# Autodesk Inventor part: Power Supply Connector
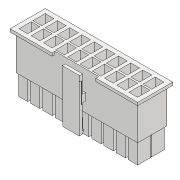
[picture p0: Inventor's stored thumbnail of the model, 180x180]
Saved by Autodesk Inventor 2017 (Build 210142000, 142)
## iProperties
Created: 2016-11
Part Number: Power Supply Connector
Material: Generic
Document SubType Name: Modeling
Designer: DanielSeverino
Density: 1 g/cm^3
Appearance: Default
Company: Autodesk Inc.
Title: C:\Users\DanielSeverino\Desktop\Power Supply Connector.stp
Author: DanielSeverino
Sending System: Autodesk Inventor 2017
Preprocessor: ST-DEVELOPER v16.5
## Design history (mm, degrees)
feature "Solid1"
body "Solid2"
